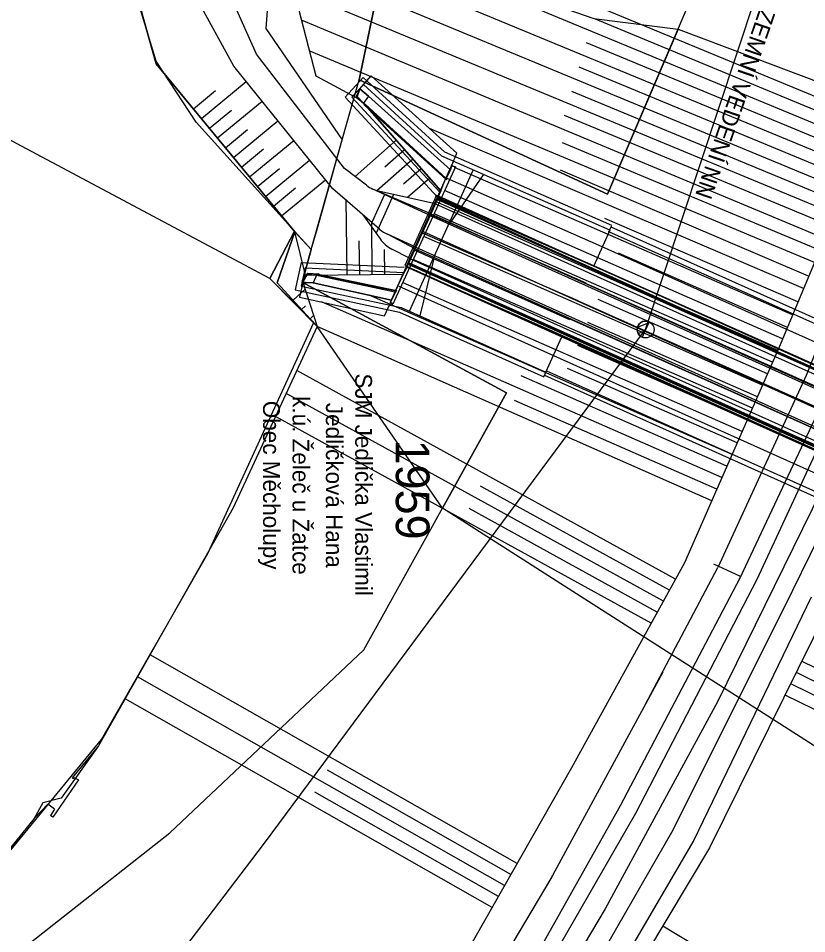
# Model space of a CAD drawing. Extents: x -801372 to -800991, y -1017235 to -1016862.
# Drawn here: x -801166.4 to -801119.6, y -1017078.6 to -1017024.1 of the extents above; entities that cross this region are included whole.
import ezdxf

# ---------------------------------------------------------------- set-up
doc = ezdxf.new("R2010")
doc.units = 0
for name, color, linetype in [('01 - nosná konstrukce', 7, 'Continuous'), ('02 - spodní stavba', 7, 'Continuous'), ('05a - kolej - svršek', 7, 'Continuous'), ('09 - stávající terén', 7, 'Continuous'), ('10 - nový terén', 7, 'Continuous'), ('15 - popisy', 7, 'Continuous'), ('16 - osy', 7, 'Continuous'), ('19 - katastr', 7, 'Continuous'), ('19b - katastr - hranice SŽDC', 7, 'Continuous'), ('19b - katastr popisy', 7, 'Continuous'), ('21g - SZDC', 7, 'Continuous'), ('26 - obvod_stavby', 7, 'Continuous'), ('27 - dočasné zábory', 7, 'Continuous'), ('Hranice parcel', 7, 'Continuous'), ('Vrstva 1 - kolej', 7, 'Continuous'), ('Vrstva 17', 7, 'Continuous'), ('Vrstva 25', 7, 'Continuous'), ('Vrstva 36', 7, 'Continuous'), ('Vrstva 48 - svahy', 7, 'Continuous')]:
    doc.layers.add(name, color=color, linetype=linetype)

# ---------------------------------------------------------------- blocks, each defined once
blk = doc.blocks.new('C724-flat-2')
at = {"layer": 'Vrstva 36'}
for p, q in [((-0.478, 0.145), (0.176, 0.397)), ((0.203, 0.457), (-0.203, -0.457)), ((-0.438, -0.241), (-0.039, -0.088))]:
    blk.add_line(p, q, dxfattribs=at)
blk.add_circle((0, 0), 0.5, dxfattribs=at)
blk.add_arc((0, 0), 0.5, 66.0786, 246.0786, dxfattribs=at)

msp = doc.modelspace()

# ---------------------------------------------------------------- linework, layer by layer
at = {"layer": '01 - nosná konstrukce'}
for p, q in [((-801141.489, -1017034.828), (-801143.243, -1017038.724)), ((-801141.511, -1017034.878), (-801092.044, -1017057.15)), ((-801141.489, -1017034.828), (-801092.021, -1017057.1)), ((-801143.243, -1017038.724), (-801093.775, -1017060.996)), ((-801143.22, -1017038.674), (-801093.753, -1017060.945))]:
    msp.add_line(p, q, dxfattribs=at)
at = {"layer": '02 - spodní stavba'}
for p, q in [((-801146.999, -1017028.796), (-801145.922, -1017027.619)), ((-801141.079, -1017032.057), (-801145.922, -1017027.619)), ((-801146.592, -1017028.795), (-801145.903, -1017028.043)), ((-801146.298, -1017028.695), (-801146.131, -1017028.292)), ((-801146.131, -1017028.292), (-801146.281, -1017028.75)), ((-801145.608, -1017028.737), (-801146.131, -1017028.292)), ((-801141.245, -1017032.311), (-801145.903, -1017028.043)), ((-801146.999, -1017028.796), (-801141.507, -1017034.736)), ((-801146.592, -1017028.795), (-801141.368, -1017034.444)), ((-801146.349, -1017028.805), (-801146.298, -1017028.695)), ((-801146.281, -1017028.75), (-801146.349, -1017028.805)), ((-801146.281, -1017028.75), (-801145.901, -1017029.16)), ((-801145.608, -1017028.737), (-801145.901, -1017029.16)), ((-801140.739, -1017033.119), (-801145.608, -1017028.737)), ((-801145.901, -1017029.16), (-801140.981, -1017033.651)), ((-801145.845, -1017029.276), (-801145.901, -1017029.16)), ((-801145.814, -1017029.21), (-801145.814, -1017029.246)), ((-801141.018, -1017033.604), (-801145.814, -1017029.21)), ((-801145.814, -1017029.246), (-801141.306, -1017034.358)), ((-801131.267, -1017036.706), (-801141.245, -1017032.311)), ((-801131.144, -1017036.433), (-801141.079, -1017032.057)), ((-801141.497, -1017034.735), (-801140.561, -1017032.612)), ((-801140.677, -1017032.875), (-801140.672, -1017032.833)), ((-801144.29, -1017040.98), (-801140.677, -1017032.875)), ((-801143.165, -1017041.523), (-801139.386, -1017033.13)), ((-801140.981, -1017033.651), (-801140.739, -1017033.119)), ((-801140.759, -1017036.29), (-801138.761, -1017033.411)), ((-801141.306, -1017034.358), (-801141.018, -1017033.604)), ((-801131.715, -1017037.706), (-801140.94, -1017033.642)), ((-801141.306, -1017034.358), (-801141.478, -1017034.761)), ((-801141.558, -1017034.618), (-801143.447, -1017038.812)), ((-801141.497, -1017034.735), (-801141.622, -1017035.008)), ((-801132.336, -1017039.099), (-801141.622, -1017035.008)), ((-801141.558, -1017034.618), (-801141.422, -1017034.679)), ((-801132.215, -1017038.824), (-801141.497, -1017034.735)), ((-801141.489, -1017034.828), (-801141.422, -1017034.679)), ((-801141.478, -1017034.761), (-801132.255, -1017038.823)), ((-801141.422, -1017034.679), (-801091.954, -1017056.95)), ((-801141.627, -1017035.135), (-801092.117, -1017057.424)), ((-801132.675, -1017039.851), (-801141.888, -1017035.793)), ((-801131.308, -1017036.798), (-801131.144, -1017036.433)), ((-801097.948, -1017051.409), (-801131.185, -1017036.524)), ((-801142.408, -1017036.87), (-801133.157, -1017040.898)), ((-801131.267, -1017036.706), (-801132.215, -1017038.824)), ((-801098.071, -1017051.683), (-801131.308, -1017036.798)), ((-801098.473, -1017052.582), (-801131.711, -1017037.697)), ((-801149.621, -1017038.64), (-801143.485, -1017038.916)), ((-801143.447, -1017038.812), (-801143.31, -1017038.874)), ((-801143.31, -1017038.874), (-801143.243, -1017038.724)), ((-801143.188, -1017038.641), (-801133.986, -1017042.769)), ((-801143.067, -1017038.435), (-801093.637, -1017060.689)), ((-801142.54, -1017041.804), (-801141.709, -1017038.4)), ((-801132.255, -1017038.823), (-801099.018, -1017053.686)), ((-801098.978, -1017053.709), (-801132.215, -1017038.824)), ((-801149.381, -1017038.951), (-801149.611, -1017040.035)), ((-801149.55, -1017039.747), (-801149.224, -1017039.274)), ((-801149.352, -1017039.393), (-801149.55, -1017039.747)), ((-801149.26, -1017039.35), (-801149.507, -1017039.793)), ((-801149.381, -1017038.951), (-801143.499, -1017039.216)), ((-801149.352, -1017039.393), (-801143.553, -1017039.321)), ((-801149.257, -1017039.368), (-801149.352, -1017039.393)), ((-801149.26, -1017039.35), (-801149.224, -1017039.274)), ((-801148.707, -1017039.376), (-801149.26, -1017039.35)), ((-801149.257, -1017039.368), (-801149.224, -1017039.274)), ((-801148.576, -1017039.388), (-801149.257, -1017039.368)), ((-801149.224, -1017039.274), (-801148.57, -1017039.297)), ((-801148.707, -1017039.376), (-801148.892, -1017039.845)), ((-801143.965, -1017040.337), (-801148.707, -1017039.376)), ((-801148.601, -1017039.432), (-801148.576, -1017039.388)), ((-801148.57, -1017039.297), (-801148.576, -1017039.388)), ((-801143.553, -1017039.321), (-801144.035, -1017040.403)), ((-801143.302, -1017038.902), (-801143.553, -1017039.321)), ((-801143.31, -1017038.874), (-801093.842, -1017061.145)), ((-801134.364, -1017042.851), (-801143.302, -1017038.902)), ((-801099.101, -1017053.983), (-801132.338, -1017039.098)), ((-801149.507, -1017039.793), (-801149.35, -1017039.827)), ((-801149.35, -1017039.827), (-801148.892, -1017039.845)), ((-801148.892, -1017039.845), (-801144.233, -1017040.875)), ((-801144.035, -1017040.403), (-801148.601, -1017039.432)), ((-801099.45, -1017054.763), (-801132.687, -1017039.878)), ((-801149.611, -1017040.035), (-801143.661, -1017041.3)), ((-801144.233, -1017040.875), (-801143.965, -1017040.337)), ((-801143.929, -1017040.298), (-801143.965, -1017040.337)), ((-801144.304, -1017041.012), (-801144.427, -1017041.286)), ((-801144.323, -1017040.941), (-801144.29, -1017040.98)), ((-801133.157, -1017040.898), (-801133.146, -1017040.902)), ((-801133.146, -1017040.902), (-801099.914, -1017055.737)), ((-801143.661, -1017041.3), (-801135.058, -1017045.16)), ((-801135.058, -1017045.16), (-801134.109, -1017043.044)), ((-801100.984, -1017057.895), (-801134.364, -1017042.851)), ((-801133.986, -1017042.769), (-801100.807, -1017057.665)), ((-801134.614, -1017044.17), (-801134.61, -1017044.161))]:
    msp.add_line(p, q, dxfattribs=at)
for points in [[(-801145.845, -1017029.276), (-801145.814, -1017029.246), (-801146.349, -1017028.805)], [(-801140.979, -1017033.718), (-801145.845, -1017029.276), (-801145.814, -1017029.21)], [(-801140.434, -1017032.945), (-801140.677, -1017032.875), (-801140.739, -1017033.119)], [(-801140.981, -1017033.651), (-801140.979, -1017033.718), (-801141.018, -1017033.604)], [(-801141.478, -1017034.761), (-801141.434, -1017034.763)], [(-801142.85, -1017037.888), (-801133.647, -1017042.017)], [(-801149.621, -1017038.64), (-801149.967, -1017040.266), (-801143.755, -1017041.587), (-801135.181, -1017045.433), (-801135.017, -1017045.068)], [(-801148.57, -1017039.297), (-801148.592, -1017039.331), (-801148.601, -1017039.432)], [(-801148.592, -1017039.331), (-801143.929, -1017040.298), (-801144.035, -1017040.403)], [(-801144.304, -1017041.012), (-801143.355, -1017038.895), (-801134.109, -1017043.043), (-801100.929, -1017057.938), (-801093.768, -1017061.156), (-801094.624, -1017063.095)], [(-801143.311, -1017038.916), (-801143.302, -1017038.902)], [(-801149.55, -1017039.747), (-801149.507, -1017039.793)], [(-801143.812, -1017040.033), (-801134.61, -1017044.161)], [(-801144.233, -1017040.875), (-801144.29, -1017040.98), (-801144.152, -1017041.111)], [(-801133.635, -1017041.989), (-801100.456, -1017056.885)], [(-801134.614, -1017044.17), (-801101.435, -1017059.065)], [(-801135.14, -1017045.342), (-801101.962, -1017060.237)], [(-801135.017, -1017045.068), (-801101.839, -1017059.964)]]:
    msp.add_lwpolyline(points, dxfattribs=at)
at = {"layer": '05a - kolej - svršek'}
for p, q in [((-801117.691, -1017044.978), (-801123.526, -1017057.407)), ((-801116.869, -1017045.275), (-801122.516, -1017057.485)), ((-801114.526, -1017046.136), (-801120.402, -1017058.145)), ((-801123.526, -1017057.407), (-801130.649, -1017070.959)), ((-801122.516, -1017057.485), (-801129.736, -1017071.4)), ((-801120.402, -1017058.145), (-801127.508, -1017072.406)), ((-801119.29, -1017058.542), (-801126.271, -1017073.005)), ((-801130.649, -1017070.959), (-801138.418, -1017084.801)), ((-801129.736, -1017071.4), (-801137.615, -1017085.081)), ((-801127.508, -1017072.406), (-801135.493, -1017086.234)), ((-801126.271, -1017073.005), (-801134.396, -1017086.885))]:
    msp.add_line(p, q, dxfattribs=at)
at = {"layer": '09 - stávající terén'}
for p, q in [((-801153.623, -1017026.95), (-801156.038, -1017022.507)), ((-801152.259, -1017026.242), (-801153.978, -1017022.39)), ((-801158.225, -1017026.81), (-801159.369, -1017022.733)), ((-801149.768, -1017023.543), (-801148.749, -1017027.534)), ((-801147.03, -1017033.036), (-801152.259, -1017026.242)), ((-801149.998, -1017036.804), (-801158.225, -1017026.81)), ((-801147.736, -1017034.239), (-801153.623, -1017026.95)), ((-801148.749, -1017027.534), (-801146.349, -1017028.805)), ((-801146.298, -1017028.695), (-801146.131, -1017028.292)), ((-801146.131, -1017028.292), (-801145.608, -1017028.737)), ((-801146.349, -1017028.805), (-801146.298, -1017028.695)), ((-801145.814, -1017029.246), (-801146.349, -1017028.805)), ((-801145.608, -1017028.737), (-801140.739, -1017033.119)), ((-801141.306, -1017034.358), (-801145.814, -1017029.246)), ((-801115.218, -1017029.281), (-801121.19, -1017043.671)), ((-801145.725, -1017034.035), (-801147.03, -1017033.036)), ((-801140.434, -1017032.945), (-801144.152, -1017041.111)), ((-801140.739, -1017033.119), (-801140.677, -1017032.875)), ((-801140.677, -1017032.875), (-801140.434, -1017032.945)), ((-801141.478, -1017034.761), (-801141.306, -1017034.358)), ((-801151.04, -1017039.834), (-801149.998, -1017036.804)), ((-801149.352, -1017039.393), (-801149.998, -1017036.804)), ((-801148.66, -1017042.443), (-801151.04, -1017039.834)), ((-801149.507, -1017039.793), (-801148.66, -1017042.443)), ((-801149.35, -1017039.827), (-801149.507, -1017039.793)), ((-801148.892, -1017039.845), (-801149.35, -1017039.827)), ((-801144.233, -1017040.875), (-801148.892, -1017039.845)), ((-801144.29, -1017040.98), (-801144.233, -1017040.875)), ((-801144.152, -1017041.111), (-801144.29, -1017040.98)), ((-801148.66, -1017042.443), (-801153.645, -1017053.228)), ((-801121.19, -1017043.671), (-801126.822, -1017056.503)), ((-801153.645, -1017053.228), (-801161.659, -1017067.387)), ((-801126.822, -1017056.503), (-801133.541, -1017068.702)), ((-801118.207, -1017059.007), (-801125.337, -1017073.453)), ((-801161.659, -1017067.387), (-801163.225, -1017069.291)), ((-801133.541, -1017068.702), (-801141.901, -1017083.399)), ((-801163.225, -1017069.291), (-801163.139, -1017069.327)), ((-801163.084, -1017069.283), (-801163.139, -1017069.327)), ((-801163.084, -1017069.283), (-801162.854, -1017069.408)), ((-801162.854, -1017069.408), (-801164.383, -1017071.63)), ((-801164.679, -1017070.859), (-801165.495, -1017071.71)), ((-801164.271, -1017071.153), (-801164.679, -1017070.859)), ((-801164.271, -1017071.153), (-801164.516, -1017071.536)), ((-801164.383, -1017071.63), (-801164.516, -1017071.536)), ((-801165.495, -1017071.71), (-801170.28, -1017077.618)), ((-801125.337, -1017073.453), (-801133.459, -1017087.061))]:
    msp.add_line(p, q, dxfattribs=at)
at = {"layer": '10 - nový terén'}
for p, q in [((-801146.133, -1017028.29), (-801145.451, -1017027.533)), ((-801140.347, -1017032.126), (-801145.451, -1017027.533)), ((-801140.661, -1017032.838), (-801140.347, -1017032.126)), ((-801144.947, -1017036.648), (-801147.726, -1017034.246)), ((-801141.935, -1017035.83), (-801145.344, -1017034.264)), ((-801141.894, -1017035.739), (-801145.344, -1017034.264)), ((-801141.627, -1017035.135), (-801145.107, -1017034.373)), ((-801144.665, -1017034.576), (-801145.416, -1017036.243)), ((-801144.123, -1017034.588), (-801145.158, -1017036.888)), ((-801145.937, -1017035.793), (-801144.924, -1017037.218)), ((-801141.939, -1017035.828), (-801092.528, -1017058.074)), ((-801141.898, -1017035.737), (-801092.487, -1017057.982)), ((-801142.793, -1017037.725), (-801144.474, -1017036.953)), ((-801142.834, -1017037.816), (-801144.474, -1017036.953)), ((-801142.793, -1017037.725), (-801093.393, -1017059.965)), ((-801143.178, -1017038.381), (-801144.225, -1017037.83)), ((-801142.834, -1017037.816), (-801093.366, -1017060.087)), ((-801149.507, -1017039.793), (-801149.705, -1017040.689)), ((-801149.705, -1017040.689), (-801144.66, -1017041.805)), ((-801144.66, -1017041.805), (-801144.327, -1017041.062))]:
    msp.add_line(p, q, dxfattribs=at)
for centre, start, end in [((-801144.509, -1017032.447), 232.5727, 245.3316), ((-801143.639, -1017035.135), 229.1591, 245.3316), ((-801143.293, -1017036.06), 215.4014, 242.2388), ((-801142.246, -1017036.611), 242.2388, 245.7619)]:
    msp.add_arc(centre, 2, start, end, dxfattribs=at)
at = {"layer": '16 - osy'}
msp.add_line((-801142.366, -1017036.776), (-801092.898, -1017059.048), dxfattribs=at)
at = {"layer": '19 - katastr'}
for p, q in [((-801147.17, -1017031.33), (-801146.17, -1017027.77)), ((-801150, -1017036.76), (-801151.48, -1017039.58)), ((-801149.01, -1017037.86), (-801150, -1017036.76))]:
    msp.add_line(p, q, dxfattribs=at)
for points in [[(-801202.21, -1016922.85), (-801202.84, -1016929.27), (-801199.62, -1016933.47), (-801189.32, -1016939.19), (-801185.94, -1016945.08), (-801185.46, -1016950.36), (-801182.14, -1016961.34), (-801180.53, -1016967.01), (-801177.89, -1016970.27), (-801173.07, -1016972.28), (-801168.07, -1016975.74), (-801164.36, -1016980.52), (-801157.66, -1016983.69), (-801154.36, -1016989.8), (-801150.62, -1016999.68), (-801150.74, -1017011.59), (-801151.72, -1017024.71), (-801147.17, -1017031.33)], [(-801150, -1017036.76), (-801155.85, -1017030.29), (-801158.23, -1017026.66), (-801159.44, -1017022.65), (-801157.64, -1017014.26), (-801156.79, -1017009.49), (-801156.11, -1017000.61), (-801157.69, -1016992.59), (-801165.08, -1016984.43), (-801171.01, -1016978.97), (-801178.02, -1016975.61), (-801179.3, -1016973.37), (-801181.87, -1016971.45), (-801184.14, -1016968.93), (-801188.76, -1016958.13), (-801189.39, -1016954.09), (-801189.23, -1016950.15), (-801190, -1016946.24)], [(-801150, -1017036.76), (-801155.85, -1017030.29), (-801158.23, -1017026.66), (-801159.44, -1017022.65), (-801157.64, -1017014.26), (-801156.79, -1017009.49), (-801156.11, -1017000.61), (-801157.69, -1016992.59), (-801165.08, -1016984.43), (-801171.01, -1016978.97), (-801178.02, -1016975.61), (-801179.3, -1016973.37), (-801181.87, -1016971.45), (-801184.14, -1016968.93), (-801188.76, -1016958.13), (-801189.39, -1016954.09), (-801189.23, -1016950.15), (-801190, -1016946.24)], [(-801146.24, -1016959.95), (-801138.7, -1016991.88), (-801146.17, -1017027.77)], [(-801151.48, -1017039.58), (-801170.76, -1017029.31), (-801179.96, -1017028.88), (-801189.85, -1017034.56), (-801195.06, -1017041.91)], [(-801151.48, -1017039.58), (-801170.76, -1017029.31), (-801179.96, -1017028.88), (-801189.85, -1017034.56), (-801195.06, -1017041.91)], [(-801170.68, -1017078.19), (-801161.48, -1017067), (-801155.16, -1017055.94), (-801148.85, -1017042.19), (-801151.48, -1017039.58)]]:
    msp.add_lwpolyline(points, dxfattribs=at)
at = {"layer": '19b - katastr - hranice SŽDC'}
for points in [[(-801146.17, -1017027.77), (-801131.4, -1017034.56), (-801122.73, -1017014.27), (-801103.54, -1016971.8), (-801099.44, -1016966.34), (-801099.01, -1016964.03), (-801100.45, -1016961.93)], [(-801149.01, -1017037.86), (-801148.65, -1017036.59), (-801147.17, -1017031.33)], [(-801179.48, -1017100.28), (-801169.74, -1017082.25), (-801157.42, -1017072.56), (-801145.88, -1017061.68), (-801137.41, -1017046.38), (-801149.55, -1017039.8), (-801149.01, -1017037.86)]]:
    msp.add_lwpolyline(points, dxfattribs=at)
at = {"layer": '21g - SZDC'}
for p, q in [((-801114.948, -1017033.699), (-801119.589, -1017045.36)), ((-801119.589, -1017045.36), (-801124.832, -1017056.776)), ((-801129.165, -1017064.953), (-801124.832, -1017056.776)), ((-801128.101, -1017062.998), (-801134.778, -1017075.313)), ((-801134.701, -1017075.184), (-801141.881, -1017087.226))]:
    msp.add_line(p, q, dxfattribs=at)
at = {"layer": '26 - obvod_stavby'}
for points in [[(-801141.216, -1017053.254), (-801148.66, -1017042.443), (-801151.48, -1017039.58), (-801150.013, -1017036.785), (-801149.01, -1017037.86), (-801147.484, -1017032.446), (-801147.484, -1017032.446), (-801146.17, -1017027.77), (-801146.17, -1017027.77), (-801144.517, -1017019.826), (-801132.211, -1017024.121), (-801127.204, -1017024.741), (-801076.63, -1017043.81), (-801086.965, -1017066.29)], [(-801085.002, -1017062.083), (-801079.49, -1017062.745), (-801060.39, -1017124.37), (-801060.39, -1017137.347), (-801071.855, -1017135.755), (-801072.61, -1017118.61), (-801086.965, -1017066.29), (-801086.638, -1017070.523), (-801095.483, -1017082.494), (-801141.216, -1017053.254), (-801148.66, -1017042.443), (-801151.48, -1017039.58)]]:
    msp.add_lwpolyline(points, dxfattribs=at)
at = {"layer": '27 - dočasné zábory'}
for points in [[(-801146.17, -1017027.77), (-801144.517, -1017019.826), (-801132.211, -1017024.121), (-801127.204, -1017024.741), (-801131.4, -1017034.56), (-801146.17, -1017027.77)], [(-801151.48, -1017039.58), (-801150, -1017036.76), (-801149.01, -1017037.86), (-801149.55, -1017039.8), (-801137.41, -1017046.38), (-801141.216, -1017053.254), (-801148.66, -1017042.443), (-801151.48, -1017039.58)]]:
    msp.add_lwpolyline(points, dxfattribs=at)
at = {"layer": 'Hranice parcel'}
msp.add_line((-801150, -1017036.76), (-801151.48, -1017039.58), dxfattribs=at)
at = {"layer": 'Vrstva 1 - kolej'}
for p, q in [((-801118.67, -1017052.166), (-801124.852, -1017064.76)), ((-801124.852, -1017064.76), (-801131.529, -1017077.075)), ((-801131.529, -1017077.075), (-801138.709, -1017089.117))]:
    msp.add_line(p, q, dxfattribs=at)
at = {"layer": 'Vrstva 17'}
for p, q in [((-801159.369, -1017022.733), (-801158.225, -1017026.81)), ((-801158.225, -1017026.81), (-801149.998, -1017036.804)), ((-801149.998, -1017036.804), (-801151.04, -1017039.834)), ((-801151.04, -1017039.834), (-801148.66, -1017042.443)), ((-801148.66, -1017042.443), (-801153.645, -1017053.228)), ((-801153.645, -1017053.228), (-801161.659, -1017067.387)), ((-801161.659, -1017067.387), (-801163.886, -1017070.497)), ((-801164.979, -1017070.769), (-801165.495, -1017071.71)), ((-801163.886, -1017070.497), (-801164.979, -1017070.769)), ((-801165.495, -1017071.71), (-801170.28, -1017077.618))]:
    msp.add_line(p, q, dxfattribs=at)
at = {"layer": 'Vrstva 25'}
for p, q in [((-801129.131, -1017042.616), (-801119.736, -1017014.228)), ((-801151.855, -1017073.26), (-801129.131, -1017042.616)), ((-801174.849, -1017103.46), (-801151.855, -1017073.26))]:
    msp.add_line(p, q, dxfattribs=at)
at = {"layer": 'Vrstva 48 - svahy'}
for p, q in [((-801115.601, -1017030.203), (-801148.438, -1017016.575)), ((-801116.176, -1017031.588), (-801148.683, -1017018.097)), ((-801116.75, -1017032.974), (-801148.982, -1017019.597)), ((-801117.325, -1017034.359), (-801149.281, -1017021.097)), ((-801117.9, -1017035.744), (-801149.58, -1017022.597)), ((-801115.888, -1017030.895), (-801132.211, -1017024.121)), ((-801118.503, -1017037.196), (-801149.596, -1017024.216)), ((-801116.463, -1017032.281), (-801132.648, -1017025.564)), ((-801119.096, -1017038.624), (-801149.131, -1017026.039)), ((-801117.038, -1017033.666), (-801133.085, -1017027.007)), ((-801155.547, -1017030.064), (-801152.881, -1017027.869)), ((-801156.023, -1017029.485), (-801154.709, -1017028.403)), ((-801117.613, -1017035.052), (-801133.522, -1017028.449)), ((-801154.593, -1017031.222), (-801151.938, -1017029.036)), ((-801155.07, -1017030.643), (-801153.756, -1017029.561)), ((-801118.188, -1017036.437), (-801133.958, -1017029.892)), ((-801153.64, -1017032.38), (-801150.996, -1017030.203)), ((-801119.738, -1017040.172), (-801141.977, -1017030.66)), ((-801154.117, -1017031.801), (-801152.803, -1017030.719)), ((-801152.687, -1017033.538), (-801150.053, -1017031.37)), ((-801143.954, -1017031.355), (-801146.403, -1017033.516)), ((-801118.795, -1017037.899), (-801134.079, -1017031.513)), ((-801153.163, -1017032.959), (-801151.849, -1017031.877)), ((-801143.458, -1017031.918), (-801144.627, -1017032.949)), ((-801151.733, -1017034.696), (-801149.111, -1017032.537)), ((-801142.962, -1017032.481), (-801145.107, -1017034.373)), ((-801152.21, -1017034.117), (-801150.896, -1017033.035)), ((-801142.466, -1017033.043), (-801143.524, -1017033.976)), ((-801120.388, -1017041.739), (-801140.495, -1017032.98)), ((-801119.438, -1017039.449), (-801134.185, -1017033.135)), ((-801150.78, -1017035.854), (-801148.168, -1017033.704)), ((-801141.97, -1017033.606), (-801143.291, -1017034.771)), ((-801151.257, -1017035.275), (-801149.948, -1017034.198)), ((-801120.986, -1017043.18), (-801141.098, -1017034.353)), ((-801146.955, -1017034.855), (-801146.899, -1017039.363)), ((-801121.579, -1017044.558), (-801141.701, -1017035.727)), ((-801120.071, -1017040.975), (-801131.56, -1017036.008)), ((-801145.438, -1017036.224), (-801145.4, -1017039.344)), ((-801122.182, -1017045.932), (-801142.322, -1017037.092)), ((-801146.175, -1017037.336), (-801146.149, -1017039.353)), ((-801144.668, -1017037.858), (-801144.65, -1017039.335)), ((-801120.699, -1017042.488), (-801130.748, -1017038.077)), ((-801122.785, -1017047.305), (-801142.944, -1017038.458)), ((-801123.388, -1017048.679), (-801143.547, -1017039.831)), ((-801121.278, -1017043.872), (-801131.339, -1017039.456)), ((-801150.093, -1017040.872), (-801149.372, -1017040.214)), ((-801124.594, -1017051.426), (-801148.397, -1017040.979)), ((-801123.991, -1017050.052), (-801145.578, -1017040.578)), ((-801121.881, -1017045.245), (-801131.946, -1017040.827)), ((-801149.588, -1017041.426), (-801149.355, -1017041.213)), ((-801149.083, -1017041.98), (-801148.87, -1017041.786)), ((-801125.196, -1017052.799), (-801148.66, -1017042.443)), ((-801122.484, -1017046.619), (-801132.558, -1017042.197)), ((-801123.087, -1017047.992), (-801133.166, -1017043.568)), ((-801127.352, -1017057.465), (-801149.871, -1017045.062)), ((-801124.292, -1017050.739), (-801136.532, -1017045.367)), ((-801123.689, -1017049.366), (-801133.769, -1017044.942)), ((-801128.076, -1017058.779), (-801150.502, -1017046.427)), ((-801124.895, -1017052.113), (-801136.919, -1017046.835)), ((-801128.799, -1017060.093), (-801151.132, -1017047.792)), ((-801127.714, -1017058.122), (-801138.95, -1017051.933)), ((-801128.437, -1017059.436), (-801139.627, -1017053.273)), ((-801123.484, -1017057.318), (-801125.068, -1017056.575)), ((-801136.775, -1017074.387), (-801158.596, -1017061.975)), ((-801119.851, -1017062.337), (-801105.466, -1017069.437)), ((-801137.516, -1017075.691), (-801159.335, -1017063.28)), ((-801120.182, -1017063.01), (-801091.534, -1017077.149)), ((-801120.514, -1017063.682), (-801106.251, -1017070.722)), ((-801120.846, -1017064.355), (-801092.44, -1017078.375)), ((-801138.258, -1017076.995), (-801160.073, -1017064.586)), ((-801137.146, -1017075.039), (-801148.055, -1017068.833)), ((-801137.887, -1017076.343), (-801148.796, -1017070.138)), ((-801128.11, -1017078.099), (-801104.352, -1017092.279))]:
    msp.add_line(p, q, dxfattribs=at)

# ---------------------------------------------------------------- block references
msp.add_blockref('C724-flat-2', (-801129.131, -1017042.616))

# ---------------------------------------------------------------- texts
at = {"layer": '15 - popisy'}
msp.add_text('NADZEMNÍ VEDENÍ NN', height=1, rotation=250.9519, dxfattribs=at).set_placement((-801121.42, -1017020.789))
at = {"layer": '19b - katastr popisy'}
for s, height, p in [('SJM Jedlička Vlastimil', 1.00005, (-801146.4, -1017045.228)), ('Obec Měcholupy', 1.00005, (-801151.877, -1017046.857)), ('k.ú. Želeč u Žatce ', 1.00005, (-801150.126, -1017046.582)), ('Jedličková Hana', 1.00005, (-801148.14, -1017046.981)), ('1959', 2, (-801143.983, -1017049.164))]:
    msp.add_text(s, height=height, rotation=270, dxfattribs=at).set_placement(p)

doc.saveas('drawing.dxf')
